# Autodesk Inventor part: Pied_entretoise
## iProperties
Shininess: 64.0
Length Units: 11269
Angle Units: 11279
Time Units: 11290
Mass Units: 11283
Length Display Precision: 3
Angle Display Precision: 2
Compacted: True
Part Number: Pied_entretoise
Document SubType Name: Modeling
Created: 2008-02
Material: Acier inoxydable - 440C
Designer: Pascal
Density: 0.0
Volumn: 0.0
Area: 0.0
PropertySet Name: Model Information
Control State: 0
Master: False
Checked Out: False
DESIGNATION: pièce
Author: Pascal
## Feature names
1. Extrusion1
